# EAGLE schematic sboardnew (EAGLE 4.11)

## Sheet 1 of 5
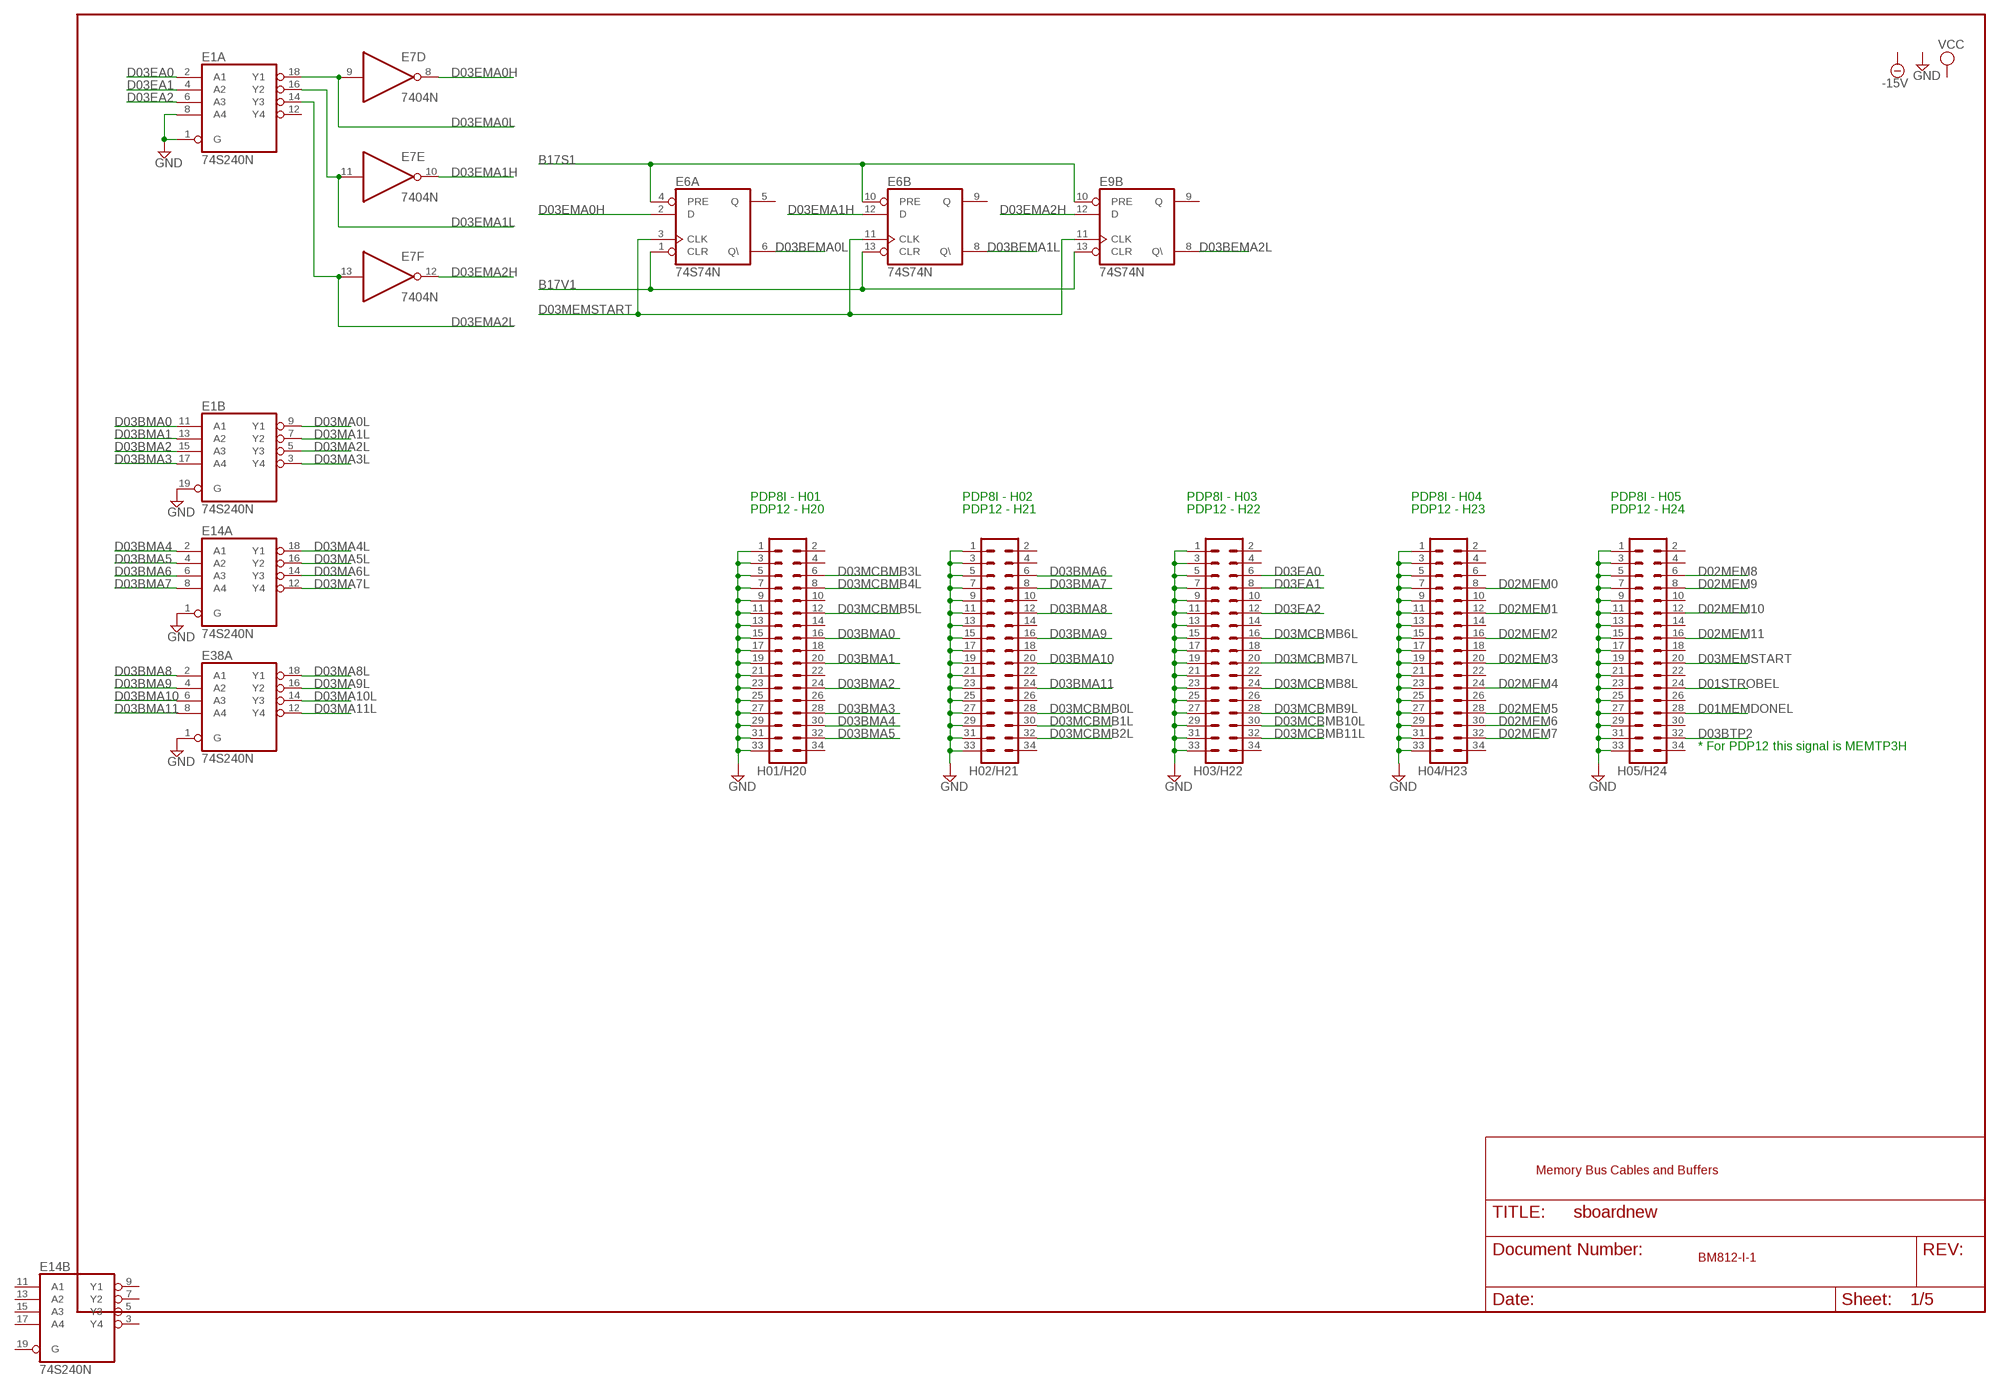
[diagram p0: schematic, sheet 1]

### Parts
E1  74S240N  [DIL20]
E6  74S74N  [DIL14]
E7  7404N  [DIL14]
E9  74S74N  [DIL14]
E14  74S240N  [DIL20]
E38  74S240N  [DIL20]
H01/H20  MA17-2  [MA17-2]
H02/H21  MA17-2  [MA17-2]
H03/H22  MA17-2  [MA17-2]
H04/H23  MA17-2  [MA17-2]
H05/H24  MA17-2  [MA17-2]

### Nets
B17S1: E6.4(A:PRE) E6.10(B:PRE) E9.10(B:PRE) ; also sheet 3,4
B17V1: E6.1(A:CLR) E6.13(B:CLR) E9.13(B:CLR) ; also sheet 3,4
D01MEMDONEL: H05/H24.28 ; also sheet 4
D01STROBEL: H05/H24.24 ; also sheet 4
D02MEM0: H04/H23.8 ; also sheet 3
D02MEM1: H04/H23.12 ; also sheet 3
D02MEM2: H04/H23.16 ; also sheet 3
D02MEM3: H04/H23.20 ; also sheet 3
D02MEM4: H04/H23.24 ; also sheet 3
D02MEM5: H04/H23.28 ; also sheet 3
D02MEM6: H04/H23.30 ; also sheet 3
D02MEM7: H04/H23.32 ; also sheet 3
D02MEM8: H05/H24.6 ; also sheet 3
D02MEM9: H05/H24.8 ; also sheet 3
D02MEM10: H05/H24.12 ; also sheet 3
D02MEM11: H05/H24.16 ; also sheet 3
D03BEMA0L: E6.6(A:Q\) ; also sheet 5
D03BEMA1L: E6.8(B:Q\) ; also sheet 5
D03BEMA2L: E9.8(B:Q\) ; also sheet 5
D03BMA0: E1.11(B:A1) H01/H20.16
D03BMA1: E1.13(B:A2) H01/H20.20
D03BMA2: E1.15(B:A3) H01/H20.24
D03BMA3: E1.17(B:A4) H01/H20.28
D03BMA4: E14.2(A:A1) H01/H20.30
D03BMA5: E14.4(A:A2) H01/H20.32
D03BMA6: E14.6(A:A3) H02/H21.6
D03BMA7: E14.8(A:A4) H02/H21.8
D03BMA8: E38.2(A:A1) H02/H21.12
D03BMA9: E38.4(A:A2) H02/H21.16
D03BMA10: E38.6(A:A3) H02/H21.20
D03BMA11: E38.8(A:A4) H02/H21.24
D03BTP2: H05/H24.32 ; also sheet 4
D03EA0: E1.2(A:A1) H03/H22.6
D03EA1: E1.4(A:A2) H03/H22.8
D03EA2: E1.6(A:A3) H03/H22.12
D03EMA0H: E6.2(A:D) E7.8(D:O) ; also sheet 4
D03EMA0L: E1.18(A:Y1) E7.9(D:I) ; also sheet 4
D03EMA1H: E6.12(B:D) E7.10(E:O) ; also sheet 4
D03EMA1L: E1.16(A:Y2) E7.11(E:I) ; also sheet 4
D03EMA2H: E7.12(F:O) E9.12(B:D) ; also sheet 4
D03EMA2L: E1.14(A:Y3) E7.13(F:I) ; also sheet 4
D03MA0L: E1.9(B:Y1) ; also sheet 5
D03MA1L: E1.7(B:Y2) ; also sheet 5
D03MA2L: E1.5(B:Y3) ; also sheet 5
D03MA3L: E1.3(B:Y4) ; also sheet 5
D03MA4L: E14.18(A:Y1) ; also sheet 5
D03MA5L: E14.16(A:Y2) ; also sheet 5
D03MA6L: E14.14(A:Y3) ; also sheet 5
D03MA7L: E14.12(A:Y4) ; also sheet 5
D03MA8L: E38.18(A:Y1) ; also sheet 5
D03MA9L: E38.16(A:Y2) ; also sheet 5
D03MA10L: E38.14(A:Y3) ; also sheet 5
D03MA11L: E38.12(A:Y4) ; also sheet 5
D03MCBMB0L: H02/H21.28 ; also sheet 2
D03MCBMB1L: H02/H21.30 ; also sheet 2
D03MCBMB2L: H02/H21.32 ; also sheet 2
D03MCBMB3L: H01/H20.6 ; also sheet 2
D03MCBMB4L: H01/H20.8 ; also sheet 2
D03MCBMB5L: H01/H20.12 ; also sheet 2
D03MCBMB6L: H03/H22.16 ; also sheet 2
D03MCBMB7L: H03/H22.20 ; also sheet 2
D03MCBMB8L: H03/H22.24 ; also sheet 2
D03MCBMB9L: H03/H22.28 ; also sheet 2
D03MCBMB10L: H03/H22.30 ; also sheet 2
D03MCBMB11L: H03/H22.32 ; also sheet 2
D03MEMSTART: E6.3(A:CLK) E6.11(B:CLK) E9.11(B:CLK) H05/H24.20 ; also sheet 4
GND [Power]: E1.1(A:G) E1.8(A:A4) E1.19(B:G) E14.1(A:G) E38.1(A:G) H01/H20.1 H01/H20.3 H01/H20.5 H01/H20.7 H01/H20.9 H01/H20.11 H01/H20.13 H01/H20.15 H01/H20.17 H01/H20.19 H01/H20.21 H01/H20.23 H01/H20.25 H01/H20.27 H01/H20.29 H01/H20.31 H01/H20.33 H02/H21.1 H02/H21.3 H02/H21.5 H02/H21.7 H02/H21.9 H02/H21.11 H02/H21.13 H02/H21.15 H02/H21.17 H02/H21.19 H02/H21.21 H02/H21.23 H02/H21.25 H02/H21.27 H02/H21.29 H02/H21.31 H02/H21.33 H03/H22.1 H03/H22.3 H03/H22.5 H03/H22.7 H03/H22.9 H03/H22.11 H03/H22.13 H03/H22.15 H03/H22.17 H03/H22.19 H03/H22.21 H03/H22.23 H03/H22.25 H03/H22.27 H03/H22.29 H03/H22.31 H03/H22.33 H04/H23.1 H04/H23.3 H04/H23.5 H04/H23.7 H04/H23.9 H04/H23.11 H04/H23.13 H04/H23.15 H04/H23.17 H04/H23.19 H04/H23.21 H04/H23.23 H04/H23.25 H04/H23.27 H04/H23.29 H04/H23.31 H04/H23.33 H05/H24.1 H05/H24.3 H05/H24.5 H05/H24.7 H05/H24.9 H05/H24.11 H05/H24.13 H05/H24.15 H05/H24.17 H05/H24.19 H05/H24.21 H05/H24.23 H05/H24.25 H05/H24.27 H05/H24.29 H05/H24.31 H05/H24.33 ; also sheet 3,4,5
Unconnected: E1.12(A:Y4) E6.5(A:Q) E6.9(B:Q) E38.3(B:Y4) E38.5(B:Y3) E38.7(B:Y2) E38.9(B:Y1) E38.11(B:A1) E38.13(B:A2) E38.15(B:A3) E38.17(B:A4) E38.19(B:G) H01/H20.2 H01/H20.4 H01/H20.10 H01/H20.14 H01/H20.18 H01/H20.22 H01/H20.26 H01/H20.34 H02/H21.2 H02/H21.4 H02/H21.10 H02/H21.14 H02/H21.18 H02/H21.22 H02/H21.26 H02/H21.34 H03/H22.2 H03/H22.4 H03/H22.10 H03/H22.14 H03/H22.18 H03/H22.22 H03/H22.26 H03/H22.34 H04/H23.2 H04/H23.4 H04/H23.6 H04/H23.10 H04/H23.14 H04/H23.18 H04/H23.22 H04/H23.26 H04/H23.34 H05/H24.2 H05/H24.4 H05/H24.10 H05/H24.14 H05/H24.18 H05/H24.22 H05/H24.26 H05/H24.30 H05/H24.34

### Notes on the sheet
- PDP8I - H01 | PDP8I - H02 | PDP8I - H03 | PDP8I - H04 | PDP8I - H05
- PDP12 - H20 | PDP12 - H21 | PDP12 - H22 | PDP12 - H23 | PDP12 - H24
- * For PDP12 this signal is MEMTP3H
- Memory Bus Cables and Buffers
- BM812-I-1

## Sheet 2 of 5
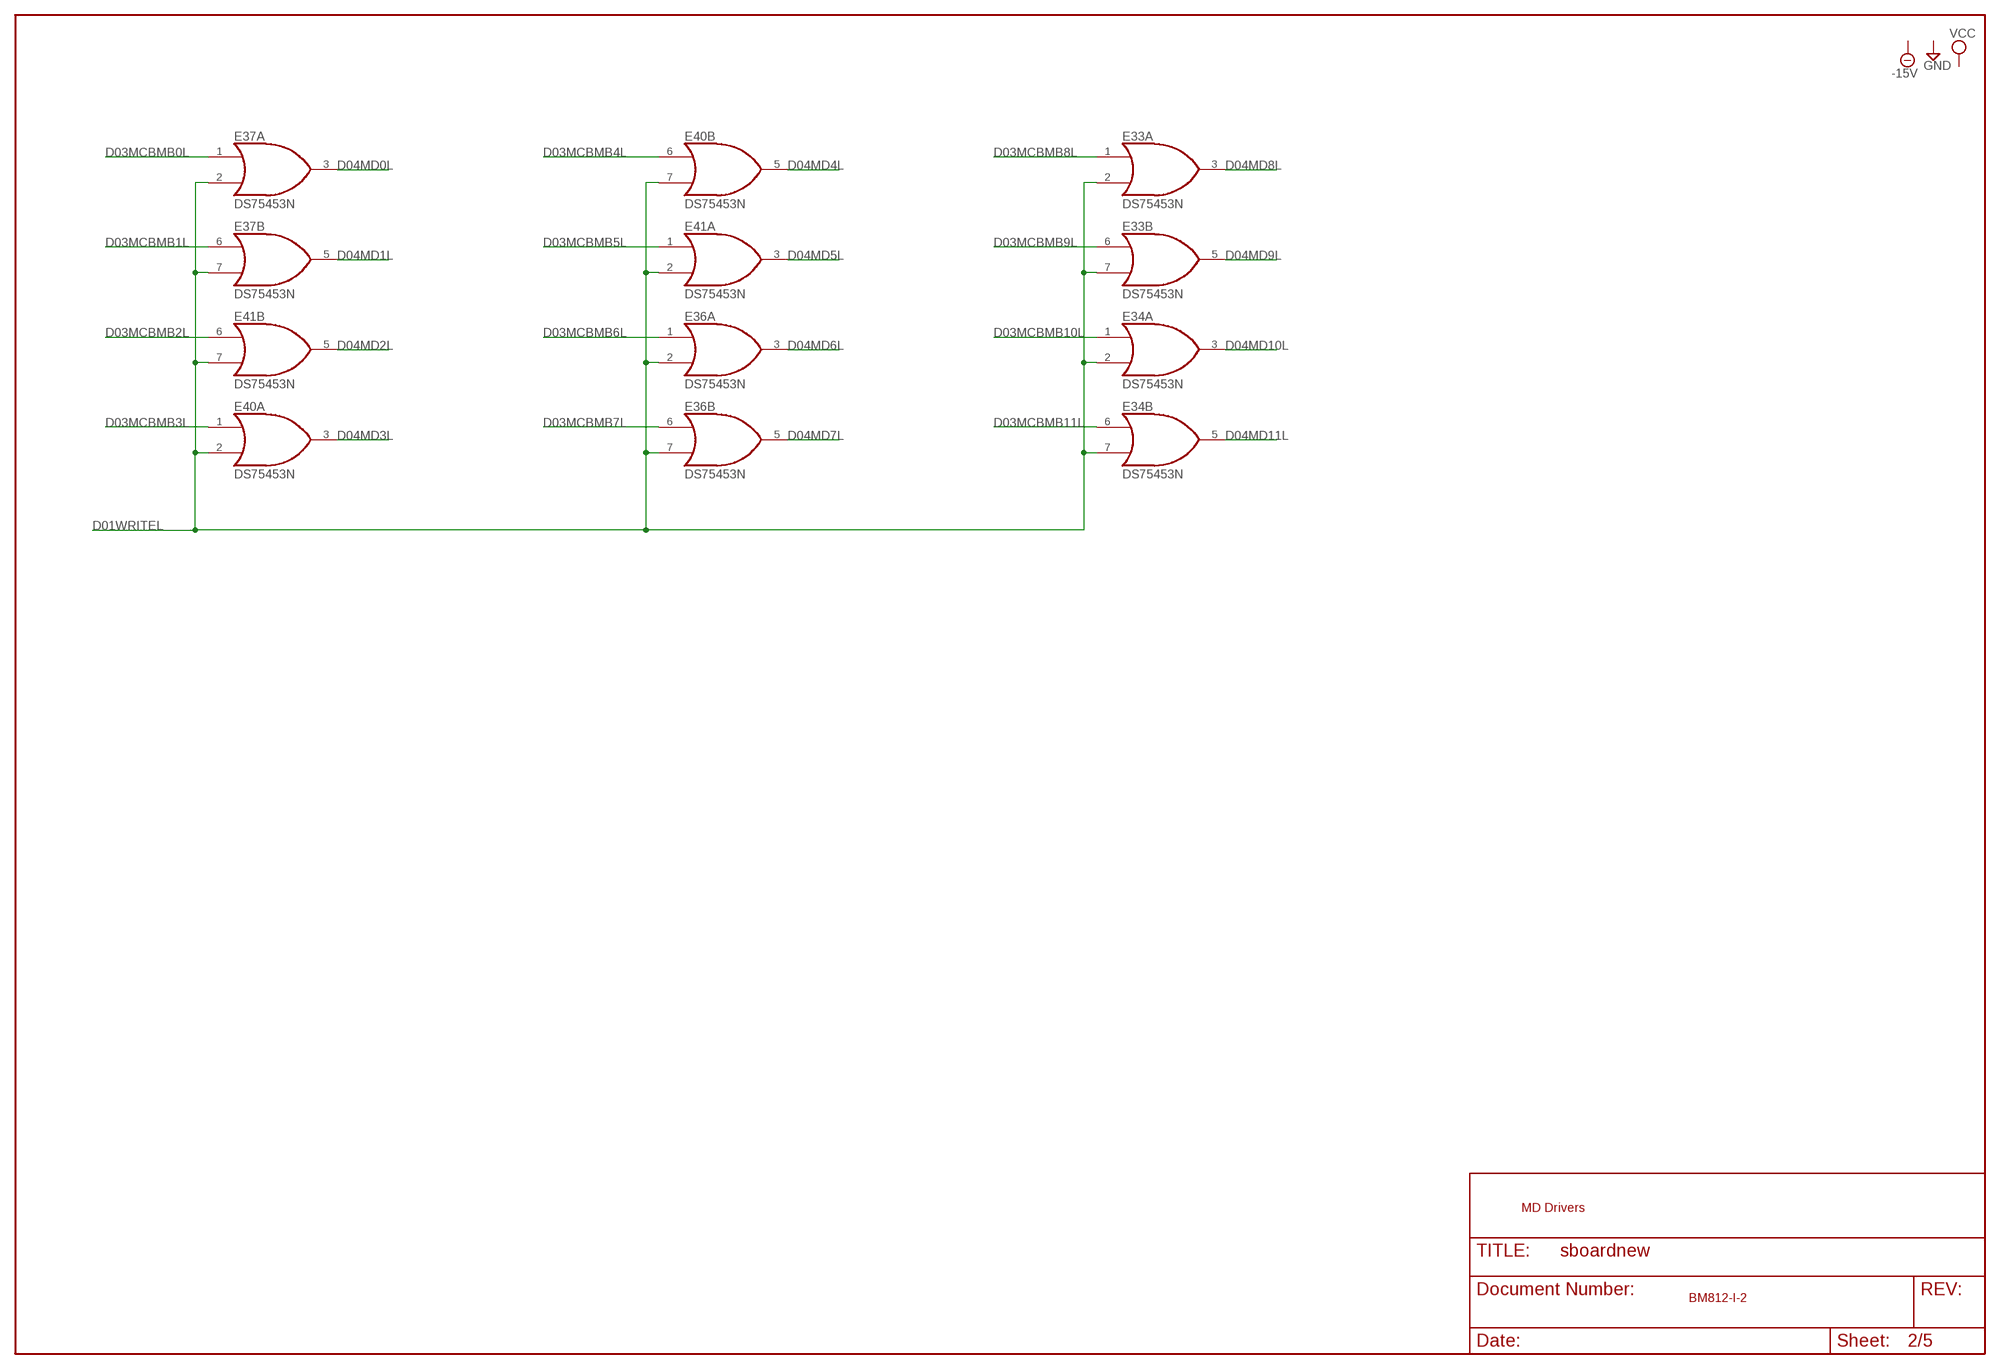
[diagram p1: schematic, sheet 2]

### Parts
E33  DS75453N  [DIL08]
E34  DS75453N  [DIL08]
E36  DS75453N  [DIL08]
E37  DS75453N  [DIL08]
E40  DS75453N  [DIL08]
E41  DS75453N  [DIL08]

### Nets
D01WRITEL: E33.2(A:I1) E33.7(B:I1) E34.2(A:I1) E34.7(B:I1) E36.2(A:I1) E36.7(B:I1) E37.2(A:I1) E37.7(B:I1) E40.2(A:I1) E40.7(B:I1) E41.2(A:I1) E41.7(B:I1) ; also sheet 3
D03MCBMB0L: E37.1(A:I0) ; also sheet 1
D03MCBMB1L: E37.6(B:I0) ; also sheet 1
D03MCBMB2L: E41.6(B:I0) ; also sheet 1
D03MCBMB3L: E40.1(A:I0) ; also sheet 1
D03MCBMB4L: E40.6(B:I0) ; also sheet 1
D03MCBMB5L: E41.1(A:I0) ; also sheet 1
D03MCBMB6L: E36.1(A:I0) ; also sheet 1
D03MCBMB7L: E36.6(B:I0) ; also sheet 1
D03MCBMB8L: E33.1(A:I0) ; also sheet 1
D03MCBMB9L: E33.6(B:I0) ; also sheet 1
D03MCBMB10L: E34.1(A:I0) ; also sheet 1
D03MCBMB11L: E34.6(B:I0) ; also sheet 1
D04MD0L: E37.3(A:O) ; also sheet 3,5
D04MD1L: E37.5(B:O) ; also sheet 3,5
D04MD2L: E41.5(B:O) ; also sheet 3,5
D04MD3L: E40.3(A:O) ; also sheet 3,5
D04MD4L: E40.5(B:O) ; also sheet 3,5
D04MD5L: E41.3(A:O) ; also sheet 3,5
D04MD6L: E36.3(A:O) ; also sheet 3,5
D04MD7L: E36.5(B:O) ; also sheet 3,5
D04MD8L: E33.3(A:O) ; also sheet 3,5
D04MD9L: E33.5(B:O) ; also sheet 3,5
D04MD10L: E34.3(A:O) ; also sheet 3,5
D04MD11L: E34.5(B:O) ; also sheet 3,5

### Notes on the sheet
- MD Drivers
- BM812-I-2

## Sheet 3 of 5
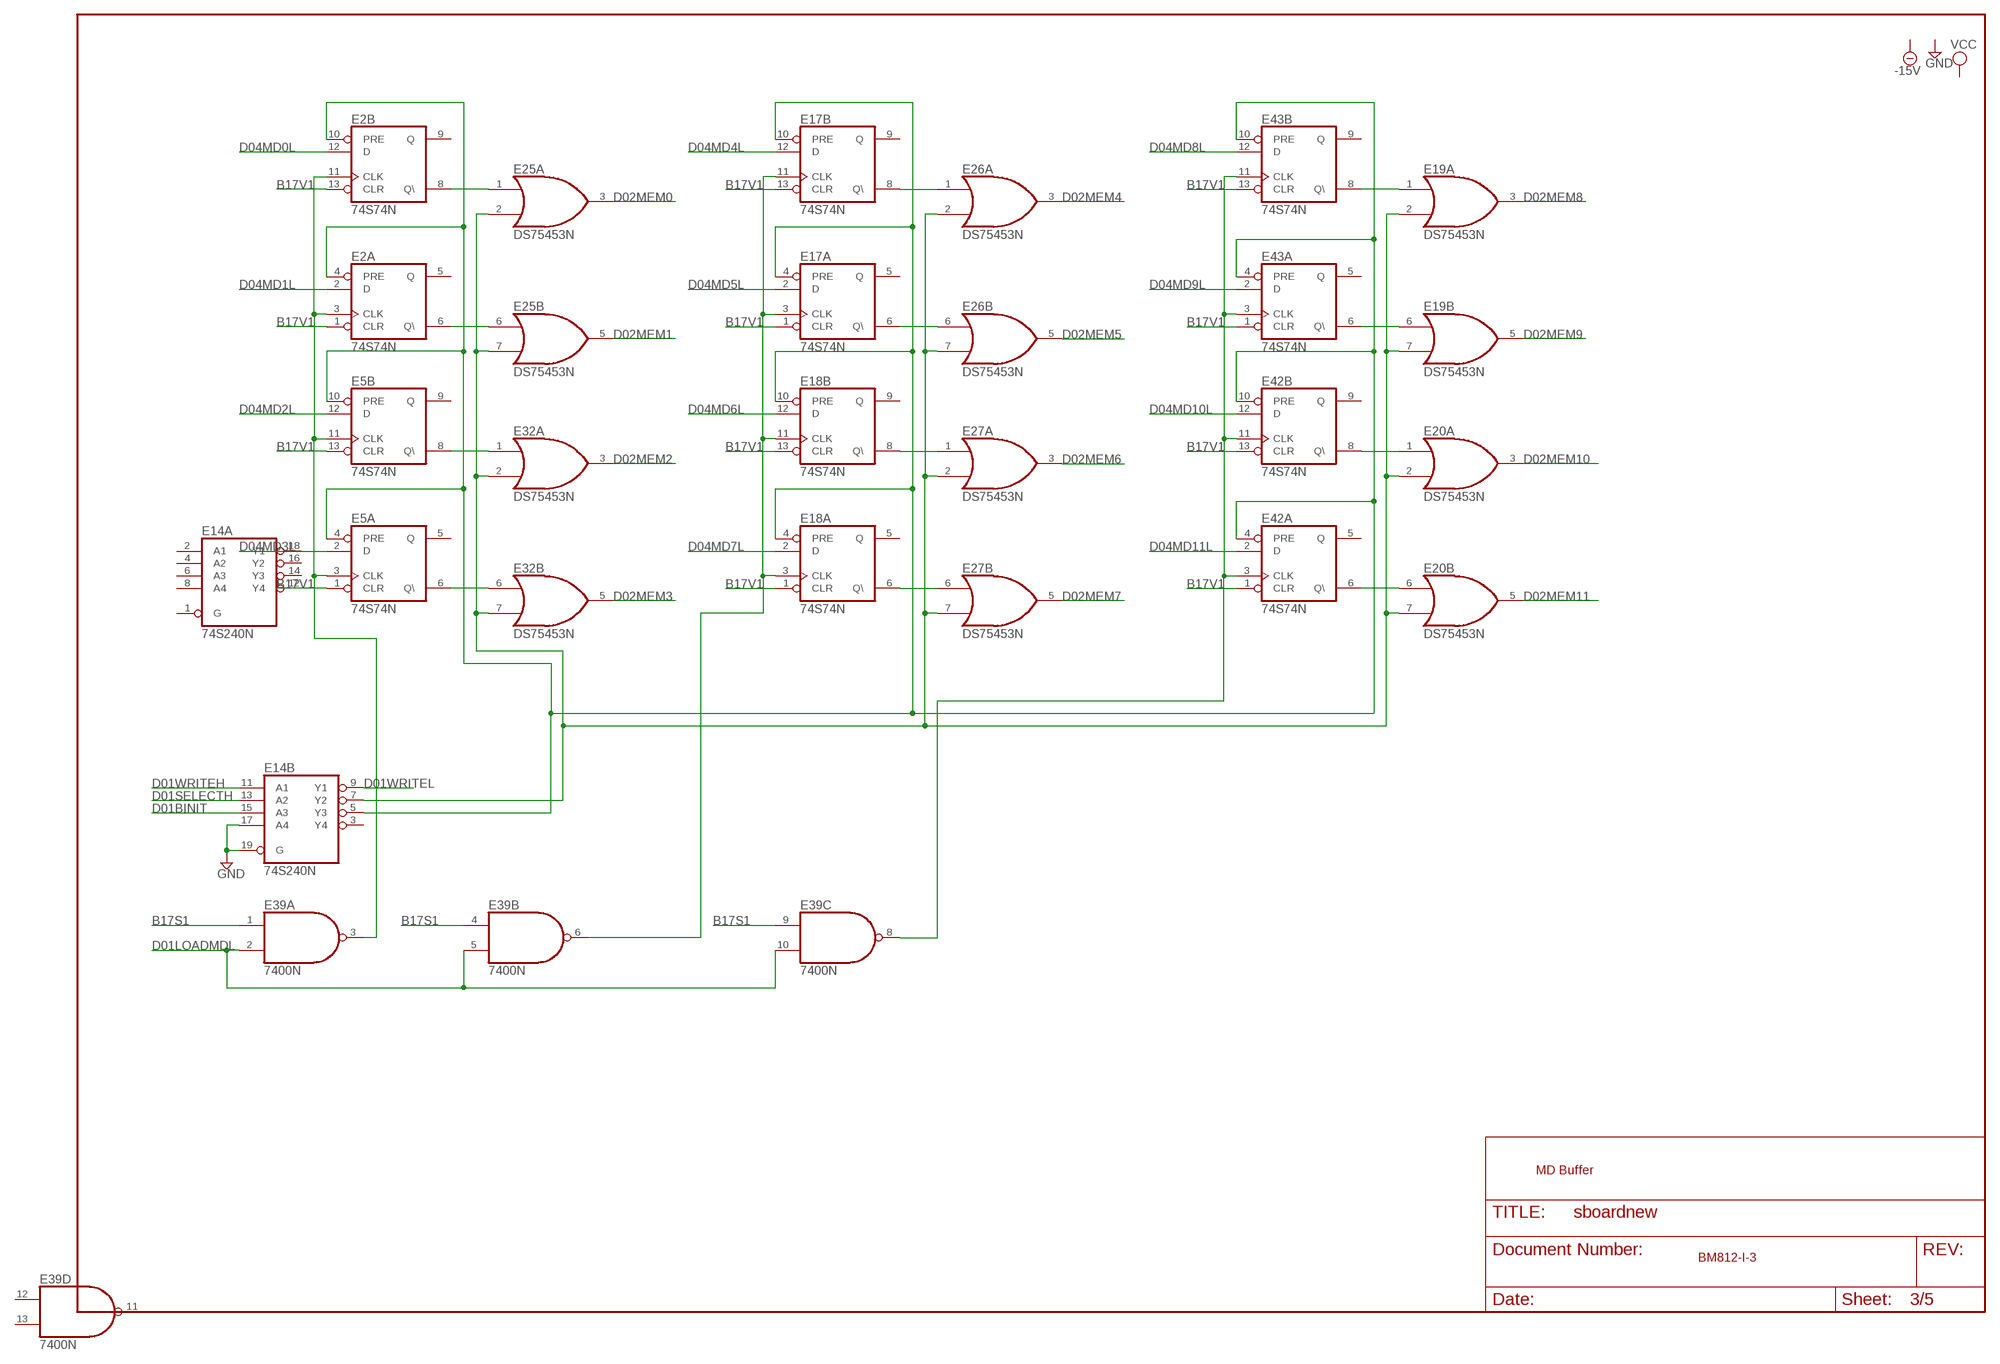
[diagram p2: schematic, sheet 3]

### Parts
E2  74S74N  [DIL14]
E5  74S74N  [DIL14]
E17  74S74N  [DIL14]
E18  74S74N  [DIL14]
E19  DS75453N  [DIL08]
E20  DS75453N  [DIL08]
E25  DS75453N  [DIL08]
E26  DS75453N  [DIL08]
E27  DS75453N  [DIL08]
E32  DS75453N  [DIL08]
E39  7400N  [DIL14]
E42  74S74N  [DIL14]
E43  74S74N  [DIL14]

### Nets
B17S1: E39.1(A:I0) E39.4(B:I0) E39.9(C:I0) ; also sheet 1,4
B17V1: E2.1(A:CLR) E2.13(B:CLR) E5.1(A:CLR) E5.13(B:CLR) E17.1(A:CLR) E17.13(B:CLR) E18.1(A:CLR) E18.13(B:CLR) E42.1(A:CLR) E42.13(B:CLR) E43.1(A:CLR) E43.13(B:CLR) ; also sheet 1,4
D01BINIT: E14.15(B:A3) ; also sheet 4
D01LOADMDL: E39.2(A:I1) E39.5(B:I1) E39.10(C:I1) ; also sheet 4
D01SELECTH: E14.13(B:A2) ; also sheet 4
D01WRITEH: E14.11(B:A1) ; also sheet 4
D01WRITEL: E14.9(B:Y1) ; also sheet 2
D02MEM0: E25.3(A:O) ; also sheet 1
D02MEM1: E25.5(B:O) ; also sheet 1
D02MEM2: E32.3(A:O) ; also sheet 1
D02MEM3: E32.5(B:O) ; also sheet 1
D02MEM4: E26.3(A:O) ; also sheet 1
D02MEM5: E26.5(B:O) ; also sheet 1
D02MEM6: E27.3(A:O) ; also sheet 1
D02MEM7: E27.5(B:O) ; also sheet 1
D02MEM8: E19.3(A:O) ; also sheet 1
D02MEM9: E19.5(B:O) ; also sheet 1
D02MEM10: E20.3(A:O) ; also sheet 1
D02MEM11: E20.5(B:O) ; also sheet 1
D04MD0L: E2.12(B:D) ; also sheet 2,5
D04MD1L: E2.2(A:D) ; also sheet 2,5
D04MD2L: E5.12(B:D) ; also sheet 2,5
D04MD3L: E5.2(A:D) ; also sheet 2,5
D04MD4L: E17.12(B:D) ; also sheet 2,5
D04MD5L: E17.2(A:D) ; also sheet 2,5
D04MD6L: E18.12(B:D) ; also sheet 2,5
D04MD7L: E18.2(A:D) ; also sheet 2,5
D04MD8L: E43.12(B:D) ; also sheet 2,5
D04MD9L: E43.2(A:D) ; also sheet 2,5
D04MD10L: E42.12(B:D) ; also sheet 2,5
D04MD11L: E42.2(A:D) ; also sheet 2,5
GND [Power]: E14.17(B:A4) E14.19(B:G) ; also sheet 1,4,5
N$8: E2.3(A:CLK) E2.11(B:CLK) E5.3(A:CLK) E5.11(B:CLK) E39.3(A:O)
N$12: E5.6(A:Q\) E32.6(B:I0)
N$14: E2.8(B:Q\) E25.1(A:I0)
N$15: E2.6(A:Q\) E25.6(B:I0)
N$16: E17.3(A:CLK) E17.11(B:CLK) E18.3(A:CLK) E18.11(B:CLK) E39.6(B:O)
N$17: E5.8(B:Q\) E32.1(A:I0)
N$21: E2.4(A:PRE) E2.10(B:PRE) E5.4(A:PRE) E5.10(B:PRE) E14.5(B:Y3) E17.4(A:PRE) E17.10(B:PRE) E18.4(A:PRE) E18.10(B:PRE) E42.4(A:PRE) E42.10(B:PRE) E43.4(A:PRE) E43.10(B:PRE)
N$22: E14.7(B:Y2) E19.2(A:I1) E19.7(B:I1) E20.2(A:I1) E20.7(B:I1) E25.2(A:I1) E25.7(B:I1) E26.2(A:I1) E26.7(B:I1) E27.2(A:I1) E27.7(B:I1) E32.2(A:I1) E32.7(B:I1)
N$24: E17.6(A:Q\) E26.6(B:I0)
N$25: E18.6(A:Q\) E27.6(B:I0)
N$26: E18.8(B:Q\) E27.1(A:I0)
N$27: E17.8(B:Q\) E26.1(A:I0)
N$29: E20.6(B:I0) E42.6(A:Q\)
N$30: E20.1(A:I0) E42.8(B:Q\)
N$41: E39.8(C:O) E42.3(A:CLK) E42.11(B:CLK) E43.3(A:CLK) E43.11(B:CLK)
N$67: E19.6(B:I0) E43.6(A:Q\)
N$68: E19.1(A:I0) E43.8(B:Q\)
Unconnected: E2.5(A:Q) E2.9(B:Q) E5.5(A:Q) E5.9(B:Q) E14.3(B:Y4) E17.5(A:Q) E17.9(B:Q) E18.5(A:Q) E18.9(B:Q) E42.5(A:Q) E42.9(B:Q) E43.5(A:Q) E43.9(B:Q)

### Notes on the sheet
- MD Buffer
- BM812-I-3

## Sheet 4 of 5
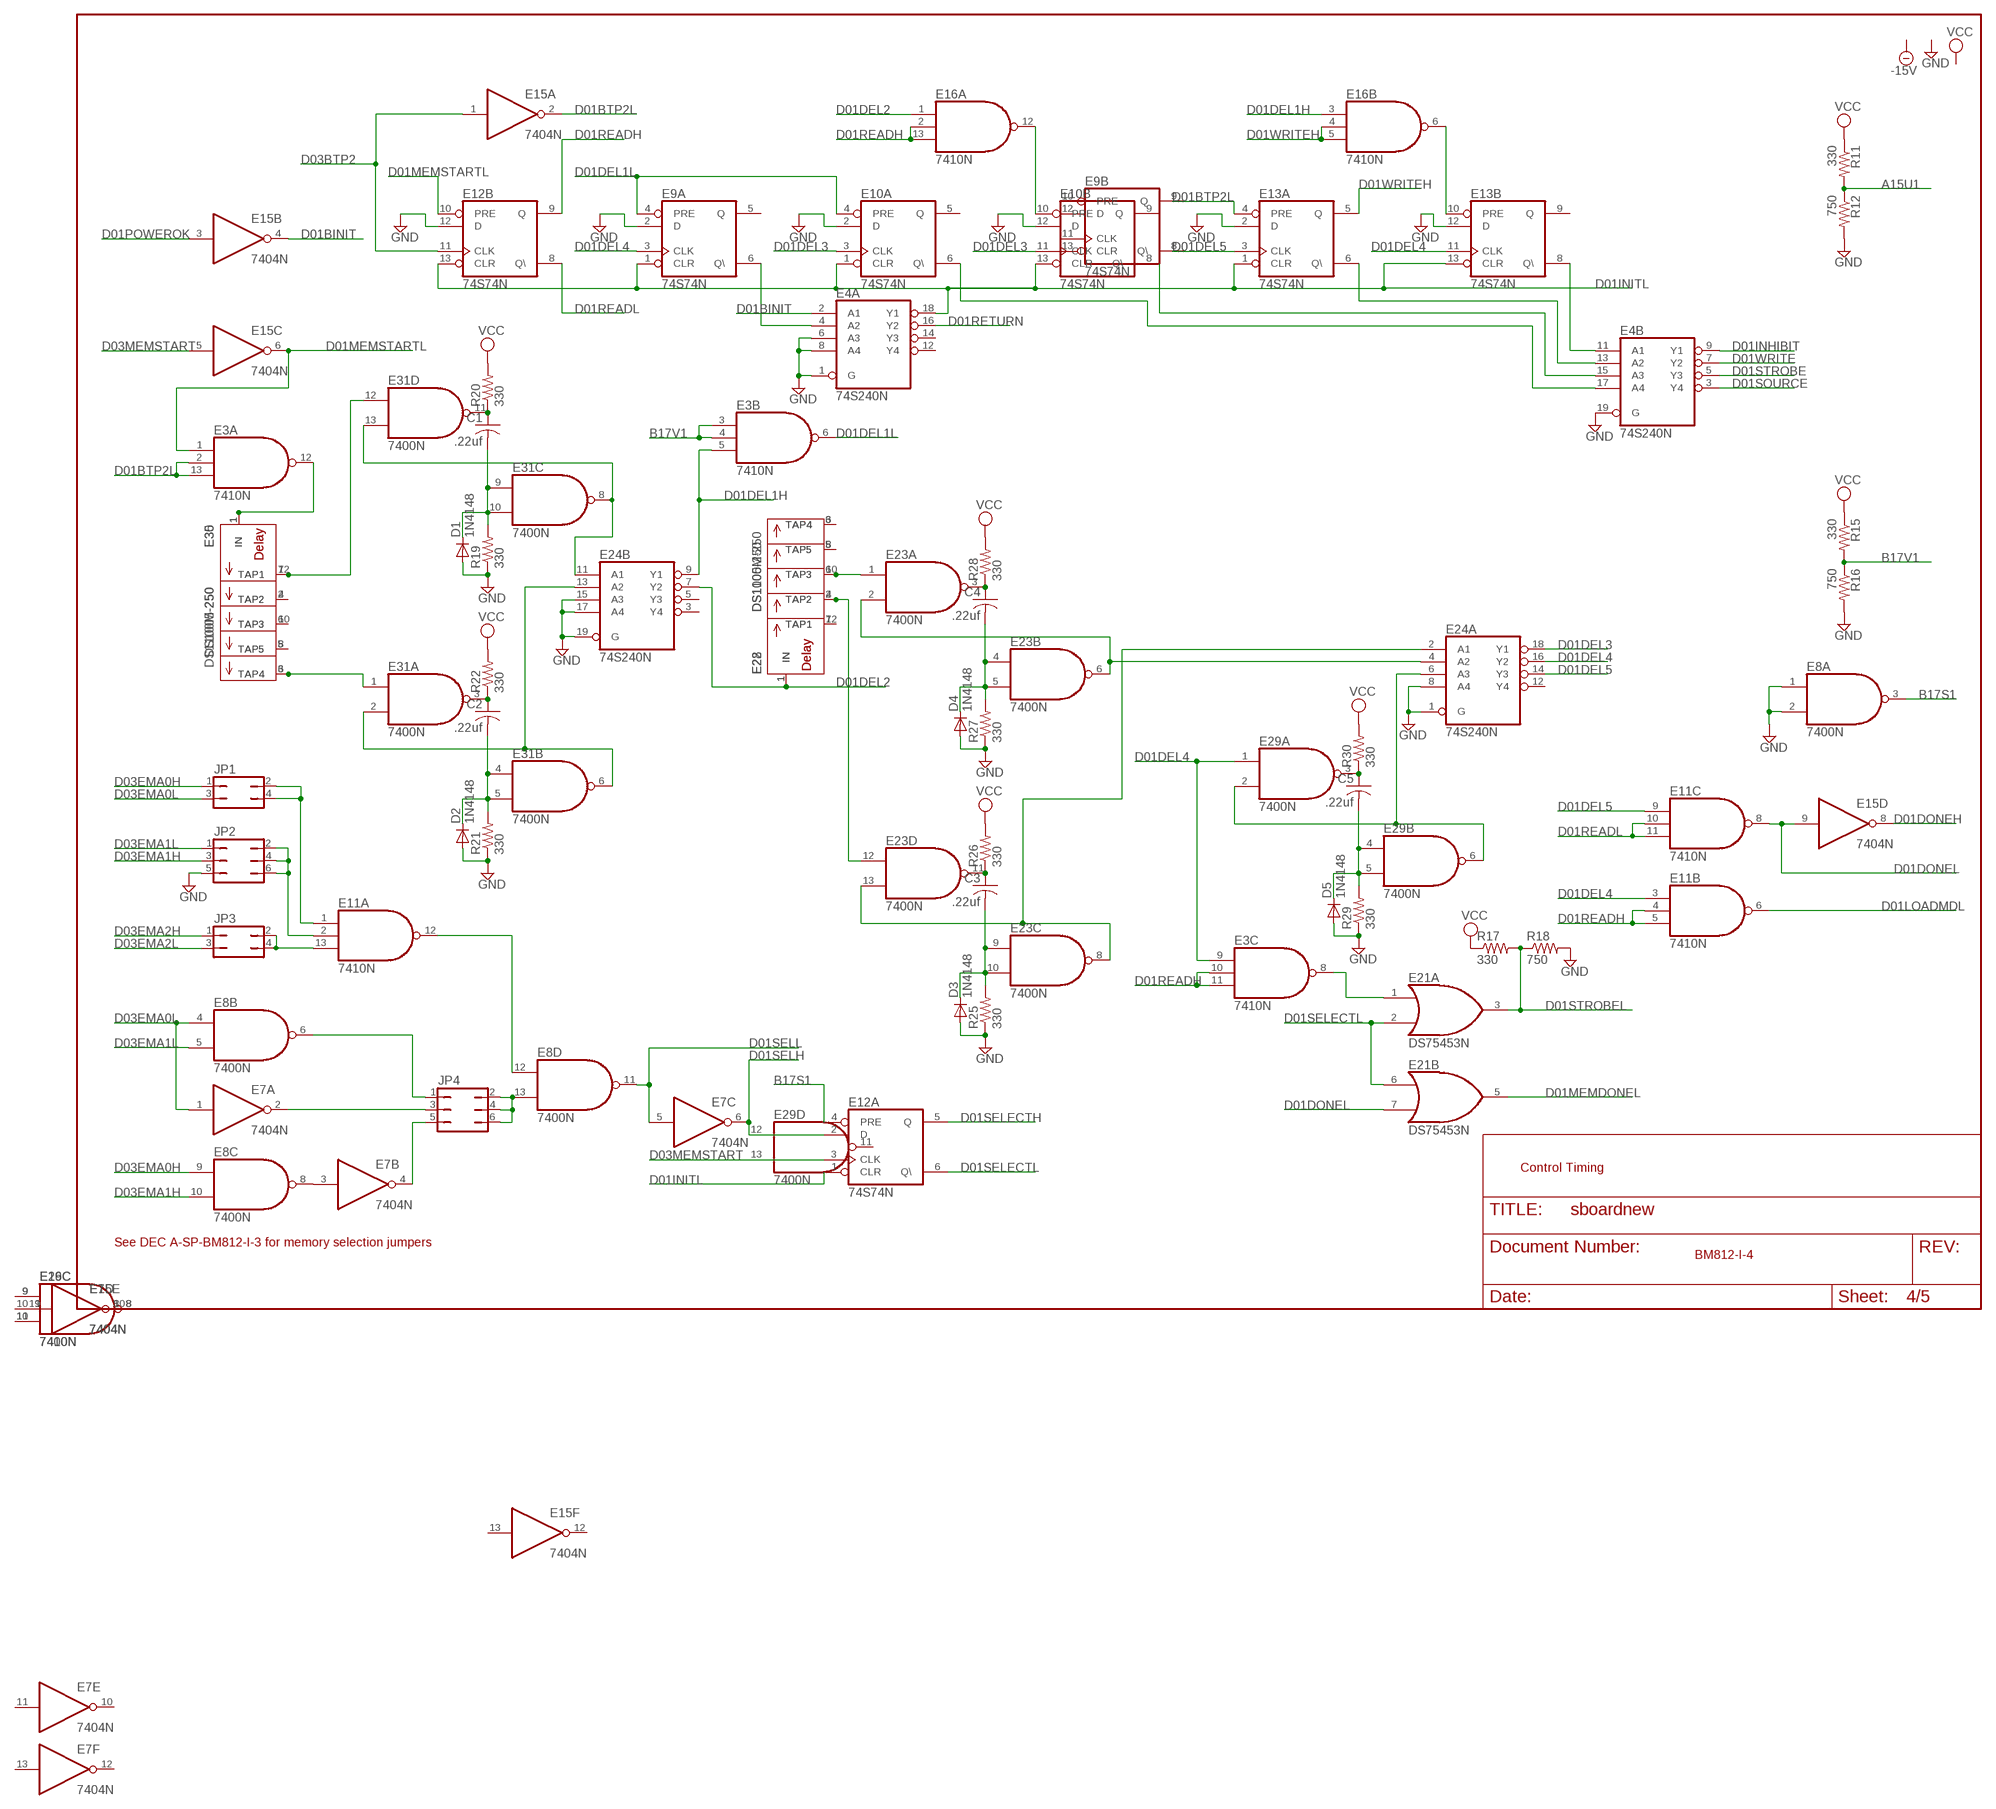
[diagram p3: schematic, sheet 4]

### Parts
C1  .22uf  C-US050-025X075  [C050-025X075]
C2  .22uf  C-US050-025X075  [C050-025X075]
C3  .22uf  C-US050-025X075  [C050-025X075]
C4  .22uf  C-US050-025X075  [C050-025X075]
C5  .22uf  C-US050-025X075  [C050-025X075]
D1  1N4148  [DO35-10]
D2  1N4148  [DO35-10]
D3  1N4148  [DO35-10]
D4  1N4148  [DO35-10]
D5  1N4148  [DO35-10]
E3  7410N  [DIL14]
E4  74S240N  [DIL20]
E8  7400N  [DIL14]
E10  74S74N  [DIL14]
E11  7410N  [DIL14]
E12  74S74N  [DIL14]
E13  74S74N  [DIL14]
E15  7404N  [DIL14]
E16  7410N  [DIL14]
E21  DS75453N  [DIL08]
E22  DS1100M-250  MXD1000  [DIL08]
E23  7400N  [DIL14]
E24  74S240N  [DIL20]
E28  DS1005-250  MXD1000P  [DIL14]
E29  7400N  [DIL14]
E30  DS1005-250  MXD1000P  [DIL14]
E31  7400N  [DIL14]
E35  DS1100M-250  MXD1000  [DIL08]
JP1  JP2Q  [JP2Q]
JP2  JP3Q  [JP3Q]
JP3  JP2Q  [JP2Q]
JP4  JP3Q  [JP3Q]
R11  330  R-US_0207/10  [0207/10]
R12  750  R-US_0207/10  [0207/10]
R15  330  R-US_0207/10  [0207/10]
R16  750  R-US_0207/10  [0207/10]
R17  330  R-US_0207/10  [0207/10]
R18  750  R-US_0207/10  [0207/10]
R19  330  R-US_0207/10  [0207/10]
R20  330  R-US_0207/10  [0207/10]
R21  330  R-US_0207/10  [0207/10]
R22  330  R-US_0207/10  [0207/10]
R25  330  R-US_0207/10  [0207/10]
R26  330  R-US_0207/10  [0207/10]
R27  330  R-US_0207/10  [0207/10]
R28  330  R-US_0207/10  [0207/10]
R29  330  R-US_0207/10  [0207/10]
R30  330  R-US_0207/10  [0207/10]

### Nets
A15U1: R11.2 R12.1 ; also sheet 5
B17S1: E8.3(A:O) E12.4(A:PRE) ; also sheet 1,3
B17V1: E3.3(B:I0) E3.4(B:I1) R15.2 R16.1 ; also sheet 1,3
D01BINIT: E4.2(A:A1) E15.4(B:O) ; also sheet 3
D01BTP2L: E3.2(A:I1) E3.13(A:I2) E13.4(A:PRE) E15.2(A:O)
D01DEL1H: E3.5(B:I2) E16.3(B:I0) E24.9(B:Y1)
D01DEL1L: E3.6(B:O) E9.4(A:PRE) E10.4(A:PRE)
D01DEL2: E16.1(A:I0) E22.1(IN) E24.7(B:Y2) E28.1(IN)
D01DEL3: E10.3(A:CLK) E10.11(B:CLK) E24.18(A:Y1)
D01DEL4: E3.9(C:I0) E9.3(A:CLK) E11.3(B:I0) E13.11(B:CLK) E24.16(A:Y2) E29.1(A:I0)
D01DEL5: E11.9(C:I0) E13.3(A:CLK) E24.14(A:Y3)
D01DONEH: E15.8(D:O) ; also sheet 5
D01DONEL: E11.8(C:O) E15.9(D:I) E21.7(B:I1)
D01INHIBIT: E4.9(B:Y1) ; also sheet 5
D01INITL: E4.18(A:Y1) E9.1(A:CLR) E10.1(A:CLR) E10.13(B:CLR) E12.1(A:CLR) E12.13(B:CLR) E13.1(A:CLR) E13.13(B:CLR)
D01LOADMDL: E11.6(B:O) ; also sheet 3
D01MEMDONEL: E21.5(B:O) ; also sheet 1
D01MEMSTARTL: E3.1(A:I0) E12.10(B:PRE) E15.6(C:O)
D01POWEROK: E15.3(B:I) ; also sheet 5
D01READH: E3.10(C:I1) E3.11(C:I2) E11.4(B:I1) E11.5(B:I2) E12.9(B:Q) E16.2(A:I1) E16.13(A:I2)
D01READL: E11.10(C:I1) E11.11(C:I2) E12.8(B:Q\) ; also sheet 5
D01RETURN: E4.16(A:Y2) ; also sheet 5
D01SELECTH: E12.5(A:Q) ; also sheet 3
D01SELECTL: E12.6(A:Q\) E21.2(A:I1) E21.6(B:I0)
D01SELH: E7.6(C:O) E12.2(A:D)
D01SELL: E7.5(C:I) E8.11(D:O)
D01SOURCE: E4.3(B:Y4) ; also sheet 5
D01STROBE: E4.5(B:Y3) ; also sheet 5
D01STROBEL: E21.3(A:O) R17.2 R18.1 ; also sheet 1
D01WRITE: E4.7(B:Y2) ; also sheet 5
D01WRITEH: E13.5(A:Q) E16.4(B:I1) E16.5(B:I2) ; also sheet 3
D03BTP2: E12.11(B:CLK) E15.1(A:I) ; also sheet 1
D03EMA0H: E8.9(C:I0) JP1.1 ; also sheet 1
D03EMA0L: E7.1(A:I) E8.4(B:I0) JP1.3 ; also sheet 1
D03EMA1H: E8.10(C:I1) JP2.3 ; also sheet 1
D03EMA1L: E8.5(B:I1) JP2.1 ; also sheet 1
D03EMA2H: JP3.1 ; also sheet 1
D03EMA2L: JP3.3 ; also sheet 1
D03MEMSTART: E12.3(A:CLK) E15.5(C:I) ; also sheet 1
GND [Power]: D1.A D2.A D3.A D4.A D5.A E4.1(A:G) E4.6(A:A3) E4.8(A:A4) E4.19(B:G) E8.1(A:I0) E8.2(A:I1) E9.2(A:D) E10.2(A:D) E10.12(B:D) E12.12(B:D) E13.2(A:D) E13.12(B:D) E24.1(A:G) E24.8(A:A4) E24.15(B:A3) E24.17(B:A4) E24.19(B:G) JP2.5 R12.2 R16.2 R18.2 R19.1 R21.1 R25.1 R27.1 R29.1 ; also sheet 1,3,5
N$3: C3.2 D3.C E23.9(C:I0) E23.10(C:I1) R25.2
N$5: C5.2 D5.C E29.4(B:I0) E29.5(B:I1) R29.2
N$7: E8.13(D:I1) JP4.2 JP4.4 JP4.6
N$9: C2.2 D2.C E31.4(B:I0) E31.5(B:I1) R21.2
N$10: E30.12(TAP1) E31.12(D:I0) E35.7(TAP1)
N$11: E22.2(TAP2) E23.12(D:I0) E28.4(TAP2)
N$13: C1.2 D1.C E31.9(C:I0) E31.10(C:I1) R19.2
N$18: E24.11(B:A1) E31.8(C:O) E31.13(D:I1)
N$19: C1.1 E31.11(D:O) R20.1
N$20: C2.1 E31.3(A:O) R22.1
N$23: E24.13(B:A2) E31.2(A:I1) E31.6(B:O)
N$28: C3.1 E23.11(D:O) R26.1
N$31: E30.6(TAP4) E31.1(A:I0) E35.3(TAP4)
N$32: E23.8(C:O) E23.13(D:I1) E24.2(A:A1)
N$33: C4.2 D4.C E23.4(B:I0) E23.5(B:I1) R27.2
N$34: C4.1 E23.3(A:O) R28.1
N$35: E3.12(A:O) E30.1(IN) E35.1(IN)
N$37: E23.2(A:I1) E23.6(B:O) E24.4(A:A2)
N$38: E22.6(TAP3) E23.1(A:I0) E28.10(TAP3)
N$39: C5.1 E29.3(A:O) R30.1
N$40: E24.6(A:A3) E29.2(A:I1) E29.6(B:O)
N$46: E10.10(B:PRE) E16.12(A:O)
N$48: E22.7(TAP1) E28.12(TAP1)
N$49: E22.3(TAP4) E28.6(TAP4)
N$50: E22.5(TAP5) E28.8(TAP5)
N$51: E30.4(TAP2) E35.2(TAP2)
N$52: E30.10(TAP3) E35.6(TAP3)
N$53: E30.8(TAP5) E35.5(TAP5)
N$73: E8.6(B:O) JP4.1
N$92: E13.10(B:PRE) E16.6(B:O)
N$94: E3.8(C:O) E21.1(A:I0)
N$96: E4.4(A:A2) E9.6(A:Q\)
N$100: E4.17(B:A4) E10.6(A:Q\)
N$101: E4.15(B:A3) E10.8(B:Q\)
N$103: E7.2(A:O) JP4.3
N$104: E4.13(B:A2) E13.6(A:Q\)
N$108: E7.3(B:I) E8.8(C:O)
N$109: E4.11(B:A1) E13.8(B:Q\)
N$111: E7.4(B:O) JP4.5
N$113: E11.13(A:I2) JP3.2 JP3.4
N$128: E11.2(A:I1) JP2.2 JP2.4 JP2.6
N$129: E11.1(A:I0) JP1.2 JP1.4
N$132: E8.12(D:I0) E11.12(A:O)
VCC [Power]: R11.1 R15.1 R17.1 R20.2 R22.2 R26.2 R28.2 R30.2 ; also sheet 5
Unconnected: E4.12(A:Y4) E4.14(A:Y3) E9.5(A:Q) E9.9(B:Q) E10.5(A:Q) E10.9(B:Q) E13.9(B:Q) E24.3(B:Y4) E24.5(B:Y3) E24.12(A:Y4) E28.2(NC) E28.3(NC) E28.5(NC) E28.9(NC) E28.11(NC) E28.13(NC) E30.2(NC) E30.3(NC) E30.5(NC) E30.9(NC) E30.11(NC) E30.13(NC)

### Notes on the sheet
- Control Timing
- See DEC A-SP-BM812-I-3 for memory selection jumpers
- BM812-I-4

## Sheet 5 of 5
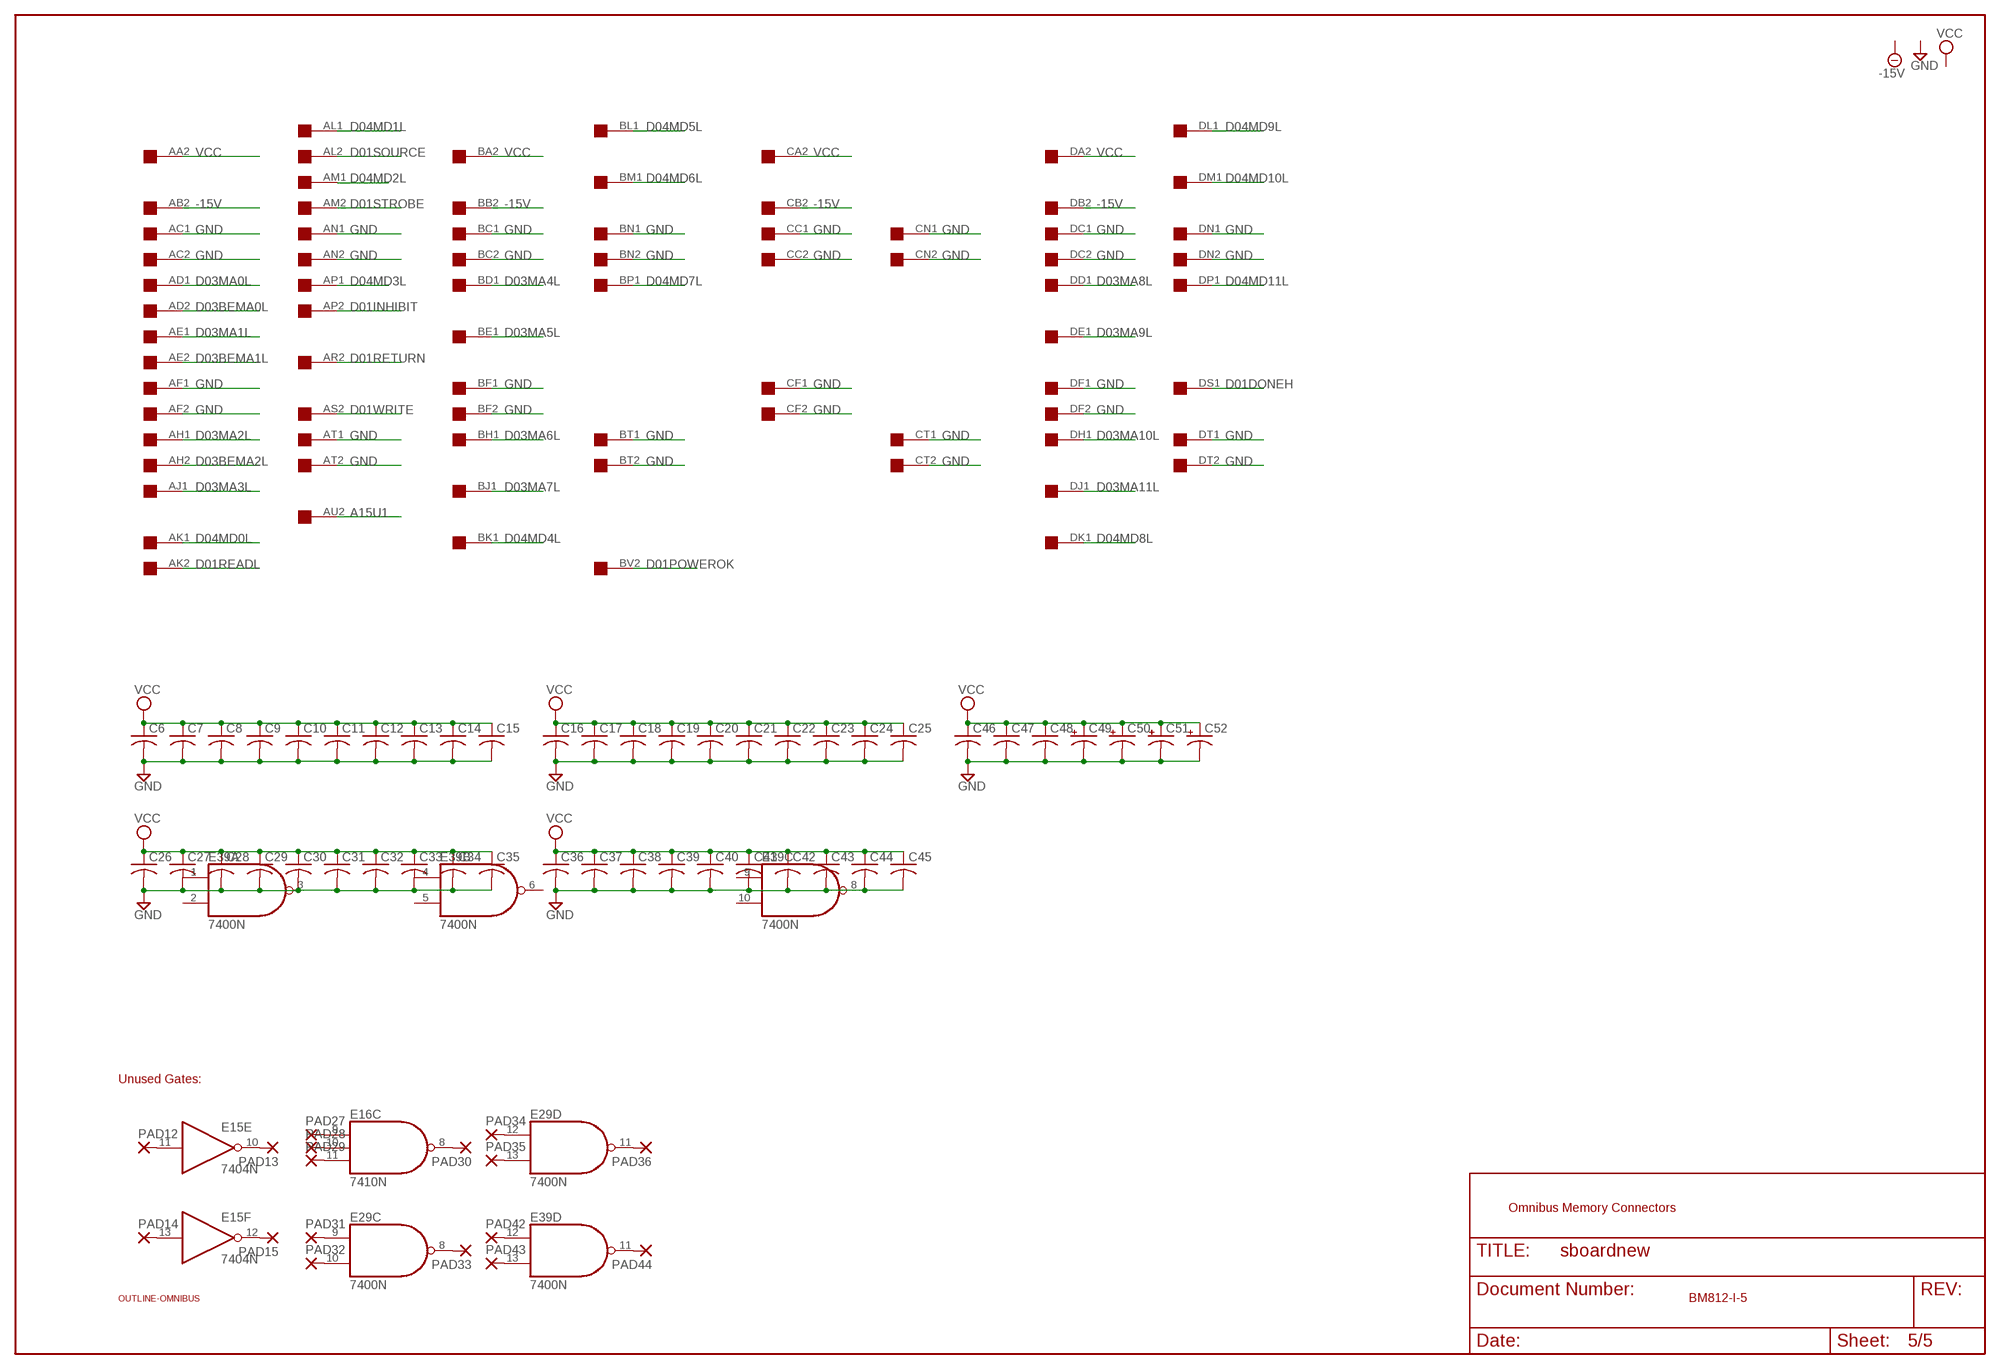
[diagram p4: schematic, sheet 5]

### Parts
C6  C-US050-025X075  [C050-025X075]
C7  C-US050-025X075  [C050-025X075]
C8  C-US050-025X075  [C050-025X075]
C9  C-US050-025X075  [C050-025X075]
C10  C-US050-025X075  [C050-025X075]
C11  C-US050-025X075  [C050-025X075]
C12  C-US050-025X075  [C050-025X075]
C13  C-US050-025X075  [C050-025X075]
C14  C-US050-025X075  [C050-025X075]
C15  C-US050-025X075  [C050-025X075]
C16  C-US050-025X075  [C050-025X075]
C17  C-US050-025X075  [C050-025X075]
C18  C-US050-025X075  [C050-025X075]
C19  C-US050-025X075  [C050-025X075]
C20  C-US050-025X075  [C050-025X075]
C21  C-US050-025X075  [C050-025X075]
C22  C-US050-025X075  [C050-025X075]
C23  C-US050-025X075  [C050-025X075]
C24  C-US050-025X075  [C050-025X075]
C25  C-US050-025X075  [C050-025X075]
C26  C-US050-025X075  [C050-025X075]
C27  C-US050-025X075  [C050-025X075]
C28  C-US050-025X075  [C050-025X075]
C29  C-US050-025X075  [C050-025X075]
C30  C-US050-025X075  [C050-025X075]
C31  C-US050-025X075  [C050-025X075]
C32  C-US050-025X075  [C050-025X075]
C33  C-US050-025X075  [C050-025X075]
C34  C-US050-025X075  [C050-025X075]
C35  C-US050-025X075  [C050-025X075]
C36  C-US050-025X075  [C050-025X075]
C37  C-US050-025X075  [C050-025X075]
C38  C-US050-025X075  [C050-025X075]
C39  C-US050-025X075  [C050-025X075]
C40  C-US050-025X075  [C050-025X075]
C41  C-US050-025X075  [C050-025X075]
C42  C-US050-025X075  [C050-025X075]
C43  C-US050-025X075  [C050-025X075]
C44  C-US050-025X075  [C050-025X075]
C45  C-US050-025X075  [C050-025X075]
C46  C-US050-025X075  [C050-025X075]
C47  C-US050-025X075  [C050-025X075]
C48  C-US050-025X075  [C050-025X075]
C49  CPOL-USE22-6AXIAL  [E22-6]
C50  CPOL-USE22-6AXIAL  [E22-6]
C51  CPOL-USE22-6AXIAL  [E22-6]
C52  CPOL-USE22-6AXIAL  [E22-6]
PAD12  1,6/0,8  [1,6/0,8]
PAD13  1,6/0,8  [1,6/0,8]
PAD14  1,6/0,8  [1,6/0,8]
PAD15  1,6/0,8  [1,6/0,8]
PAD27  1,6/0,8  [1,6/0,8]
PAD28  1,6/0,8  [1,6/0,8]
PAD29  1,6/0,8  [1,6/0,8]
PAD30  1,6/0,8  [1,6/0,8]
PAD31  1,6/0,8  [1,6/0,8]
PAD32  1,6/0,8  [1,6/0,8]
PAD33  1,6/0,8  [1,6/0,8]
PAD34  1,6/0,8  [1,6/0,8]
PAD35  1,6/0,8  [1,6/0,8]
PAD36  1,6/0,8  [1,6/0,8]
PAD42  1,6/0,8  [1,6/0,8]
PAD43  1,6/0,8  [1,6/0,8]
PAD44  1,6/0,8  [1,6/0,8]
U$1  QUAD  [EDGE-CON8]
U$2  OUTLINE-OMNIBUS  [OMNIBUS]

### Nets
-15V [Power]: U$1.AB2 U$1.BB2 U$1.CB2 U$1.DB2
A15U1: U$1.AU2 ; also sheet 4
D01DONEH: U$1.DS1 ; also sheet 4
D01INHIBIT: U$1.AP2 ; also sheet 4
D01POWEROK: U$1.BV2 ; also sheet 4
D01READL: U$1.AK2 ; also sheet 4
D01RETURN: U$1.AR2 ; also sheet 4
D01SOURCE: U$1.AL2 ; also sheet 4
D01STROBE: U$1.AM2 ; also sheet 4
D01WRITE: U$1.AS2 ; also sheet 4
D03BEMA0L: U$1.AD2 ; also sheet 1
D03BEMA1L: U$1.AE2 ; also sheet 1
D03BEMA2L: U$1.AH2 ; also sheet 1
D03MA0L: U$1.AD1 ; also sheet 1
D03MA1L: U$1.AE1 ; also sheet 1
D03MA2L: U$1.AH1 ; also sheet 1
D03MA3L: U$1.AJ1 ; also sheet 1
D03MA4L: U$1.BD1 ; also sheet 1
D03MA5L: U$1.BE1 ; also sheet 1
D03MA6L: U$1.BH1 ; also sheet 1
D03MA7L: U$1.BJ1 ; also sheet 1
D03MA8L: U$1.DD1 ; also sheet 1
D03MA9L: U$1.DE1 ; also sheet 1
D03MA10L: U$1.DH1 ; also sheet 1
D03MA11L: U$1.DJ1 ; also sheet 1
D04MD0L: U$1.AK1 ; also sheet 2,3
D04MD1L: U$1.AL1 ; also sheet 2,3
D04MD2L: U$1.AM1 ; also sheet 2,3
D04MD3L: U$1.AP1 ; also sheet 2,3
D04MD4L: U$1.BK1 ; also sheet 2,3
D04MD5L: U$1.BL1 ; also sheet 2,3
D04MD6L: U$1.BM1 ; also sheet 2,3
D04MD7L: U$1.BP1 ; also sheet 2,3
D04MD8L: U$1.DK1 ; also sheet 2,3
D04MD9L: U$1.DL1 ; also sheet 2,3
D04MD10L: U$1.DM1 ; also sheet 2,3
D04MD11L: U$1.DP1 ; also sheet 2,3
GND [Power]: C6.2 C7.2 C8.2 C9.2 C10.2 C11.2 C12.2 C13.2 C14.2 C15.2 C16.2 C17.2 C18.2 C19.2 C20.2 C21.2 C22.2 C23.2 C24.2 C25.2 C26.2 C27.2 C28.2 C29.2 C30.2 C31.2 C32.2 C33.2 C34.2 C35.2 C36.2 C37.2 C38.2 C39.2 C40.2 C41.2 C42.2 C43.2 C44.2 C45.2 C46.2 C47.2 C48.2 C49.- C50.- C51.- C52.- U$1.AC1 U$1.AC2 U$1.AF1 U$1.AF2 U$1.AN1 U$1.AN2 U$1.AT1 U$1.AT2 U$1.BC1 U$1.BC2 U$1.BF1 U$1.BF2 U$1.BN1 U$1.BN2 U$1.BT1 U$1.BT2 U$1.CC1 U$1.CC2 U$1.CF1 U$1.CF2 U$1.CN1 U$1.CN2 U$1.CT1 U$1.CT2 U$1.DC1 U$1.DC2 U$1.DF1 U$1.DF2 U$1.DN1 U$1.DN2 U$1.DT1 U$1.DT2 ; also sheet 1,3,4
N$54: E15.11(E:I) PAD12.1(P)
N$55: E15.10(E:O) PAD13.1(P)
N$56: E15.13(F:I) PAD14.1(P)
N$57: E15.12(F:O) PAD15.1(P)
N$71: E16.9(C:I0) PAD27.1(P)
N$72: E16.10(C:I1) PAD28.1(P)
N$74: E16.11(C:I2) PAD29.1(P)
N$75: E16.8(C:O) PAD30.1(P)
N$76: E29.9(C:I0) PAD31.1(P)
N$77: E29.10(C:I1) PAD32.1(P)
N$78: E29.8(C:O) PAD33.1(P)
N$79: E29.12(D:I0) PAD34.1(P)
N$80: E29.13(D:I1) PAD35.1(P)
N$81: E29.11(D:O) PAD36.1(P)
N$87: E39.12(D:I0) PAD42.1(P)
N$88: E39.13(D:I1) PAD43.1(P)
N$89: E39.11(D:O) PAD44.1(P)
VCC [Power]: C6.1 C7.1 C8.1 C9.1 C10.1 C11.1 C12.1 C13.1 C14.1 C15.1 C16.1 C17.1 C18.1 C19.1 C20.1 C21.1 C22.1 C23.1 C24.1 C25.1 C26.1 C27.1 C28.1 C29.1 C30.1 C31.1 C32.1 C33.1 C34.1 C35.1 C36.1 C37.1 C38.1 C39.1 C40.1 C41.1 C42.1 C43.1 C44.1 C45.1 C46.1 C47.1 C48.1 C49.+ C50.+ C51.+ C52.+ U$1.AA2 U$1.BA2 U$1.CA2 U$1.DA2 ; also sheet 4
Unconnected: U$1.AA1 U$1.AB1 U$1.AJ2 U$1.AR1 U$1.AS1 U$1.AU1 U$1.AV1 U$1.AV2 U$1.BA1 U$1.BB1 U$1.BD2 U$1.BE2 U$1.BH2 U$1.BJ2 U$1.BK2 U$1.BL2 U$1.BM2 U$1.BP2 U$1.BR1 U$1.BR2 U$1.BS1 U$1.BS2 U$1.BU1 U$1.BU2 U$1.BV1 U$1.CA1 U$1.CB1 U$1.CD1 U$1.CD2 U$1.CE1 U$1.CE2 U$1.CH1 U$1.CH2 U$1.CJ1 U$1.CJ2 U$1.CK1 U$1.CK2 U$1.CL1 U$1.CL2 U$1.CM1 U$1.CM2 U$1.CP1 U$1.CP2 U$1.CR1 U$1.CR2 U$1.CS1 U$1.CS2 U$1.CU1 U$1.CU2 U$1.CV1 U$1.CV2 U$1.DA1 U$1.DB1 U$1.DD2 U$1.DE2 U$1.DH2 U$1.DJ2 U$1.DK2 U$1.DL2 U$1.DM2 U$1.DP2 U$1.DR1 U$1.DR2 U$1.DS2 U$1.DU1 U$1.DU2 U$1.DV1 U$1.DV2

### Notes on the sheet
- Unused Gates:
- Omnibus Memory Connectors
- BM812-I-5

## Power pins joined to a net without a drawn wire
GND: E1.10(P:GND) E2.7(P:GND) E3.7(P:GND) E4.10(P:GND) E5.7(P:GND) E6.7(P:GND) E7.7(P:GND) E8.7(P:GND) E9.7(P:GND) E10.7(P:GND) E11.7(P:GND) E12.7(P:GND) E13.7(P:GND) E14.10(P:GND) E15.7(P:GND) E16.7(P:GND) E17.7(P:GND) E18.7(P:GND) E19.4(P:GND) E20.4(P:GND) E21.4(P:GND) E22.4(GND) E23.7(P:GND) E24.10(P:GND) E25.4(P:GND) E26.4(P:GND) E27.4(P:GND) E28.7(GND) E29.7(P:GND) E30.7(GND) E31.7(P:GND) E32.4(P:GND) E33.4(P:GND) E34.4(P:GND) E35.4(GND) E36.4(P:GND) E37.4(P:GND) E38.10(P:GND) E39.7(P:GND) E40.4(P:GND) E41.4(P:GND) E42.7(P:GND) E43.7(P:GND)
VCC: E1.20(P:VCC) E2.14(P:VCC) E3.14(P:VCC) E4.20(P:VCC) E5.14(P:VCC) E6.14(P:VCC) E7.14(P:VCC) E8.14(P:VCC) E9.14(P:VCC) E10.14(P:VCC) E11.14(P:VCC) E12.14(P:VCC) E13.14(P:VCC) E14.20(P:VCC) E15.14(P:VCC) E16.14(P:VCC) E17.14(P:VCC) E18.14(P:VCC) E19.8(P:VCC) E20.8(P:VCC) E21.8(P:VCC) E22.8(VCC) E23.14(P:VCC) E24.20(P:VCC) E25.8(P:VCC) E26.8(P:VCC) E27.8(P:VCC) E28.14(VCC) E29.14(P:VCC) E30.14(VCC) E31.14(P:VCC) E32.8(P:VCC) E33.8(P:VCC) E34.8(P:VCC) E35.8(VCC) E36.8(P:VCC) E37.8(P:VCC) E38.20(P:VCC) E39.14(P:VCC) E40.8(P:VCC) E41.8(P:VCC) E42.14(P:VCC) E43.14(P:VCC)

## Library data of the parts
C1-C48 = rcl:C-US: CAPACITOR, American symbol
C49-C52 = rcl:CPOL-US: POLARIZED CAPACITOR, American symbol
D1-D5 = diode:1N4148: DIODE
E1 E4 E14 E24 E38 = 74xx-jameco:74*240: Octal BUFFER and LINE DRIVER, 3-state
E2 E5 E6 E9 E10 E12 E13 E17 E18 E42 E43 = 74xx-jameco:74*74: Dual D type positive edge triggered FLIP FLOP, preset and clear
E3 E11 E16 = 74xx-jameco:74*10: Triple 3-input NAND gate
E7 E15 = 74xx-jameco:74*04: Hex INVERTER
E8 E23 E29 E31 E39 = 74xx-jameco:74*00: Quad 2-input NAND gate
E19-E21 E25-E27 E32-E34 E36 E37 E40 E41 = 74xx-jameco:DS75453: Quad 2-input NAND gate, open collector output
E22 E35 = maxim:MXD1000: DELAY LINE
E28 E30 = maxim:MXD1000P: DELAY LINE
H01/H20 H02/H21 H03/H22 H04/H23 H05/H24 = con-lstb:MA17-2: PIN HEADER
JP1 JP3 = jumper:JP2Q: JUMPER
JP2 JP4 = jumper:JP3Q: JUMPER
PAD12-PAD15 PAD27-PAD36 PAD42-PAD44 = wirepad:1,6/0,8: THROUGH-HOLE PAD
R11 R12 R15-R22 R25-R30 = rcl:R-US_: RESISTOR, American symbol
U$1 = dec-con:QUAD: Quad-Height DEC board
U$2 = dec-con:OUTLINE-*: Board outlines for DEC boards.

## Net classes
1 Power: width 0.635 mm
